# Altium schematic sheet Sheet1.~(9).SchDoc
size A4; SheetNumber: 2; SheetTotal: 2
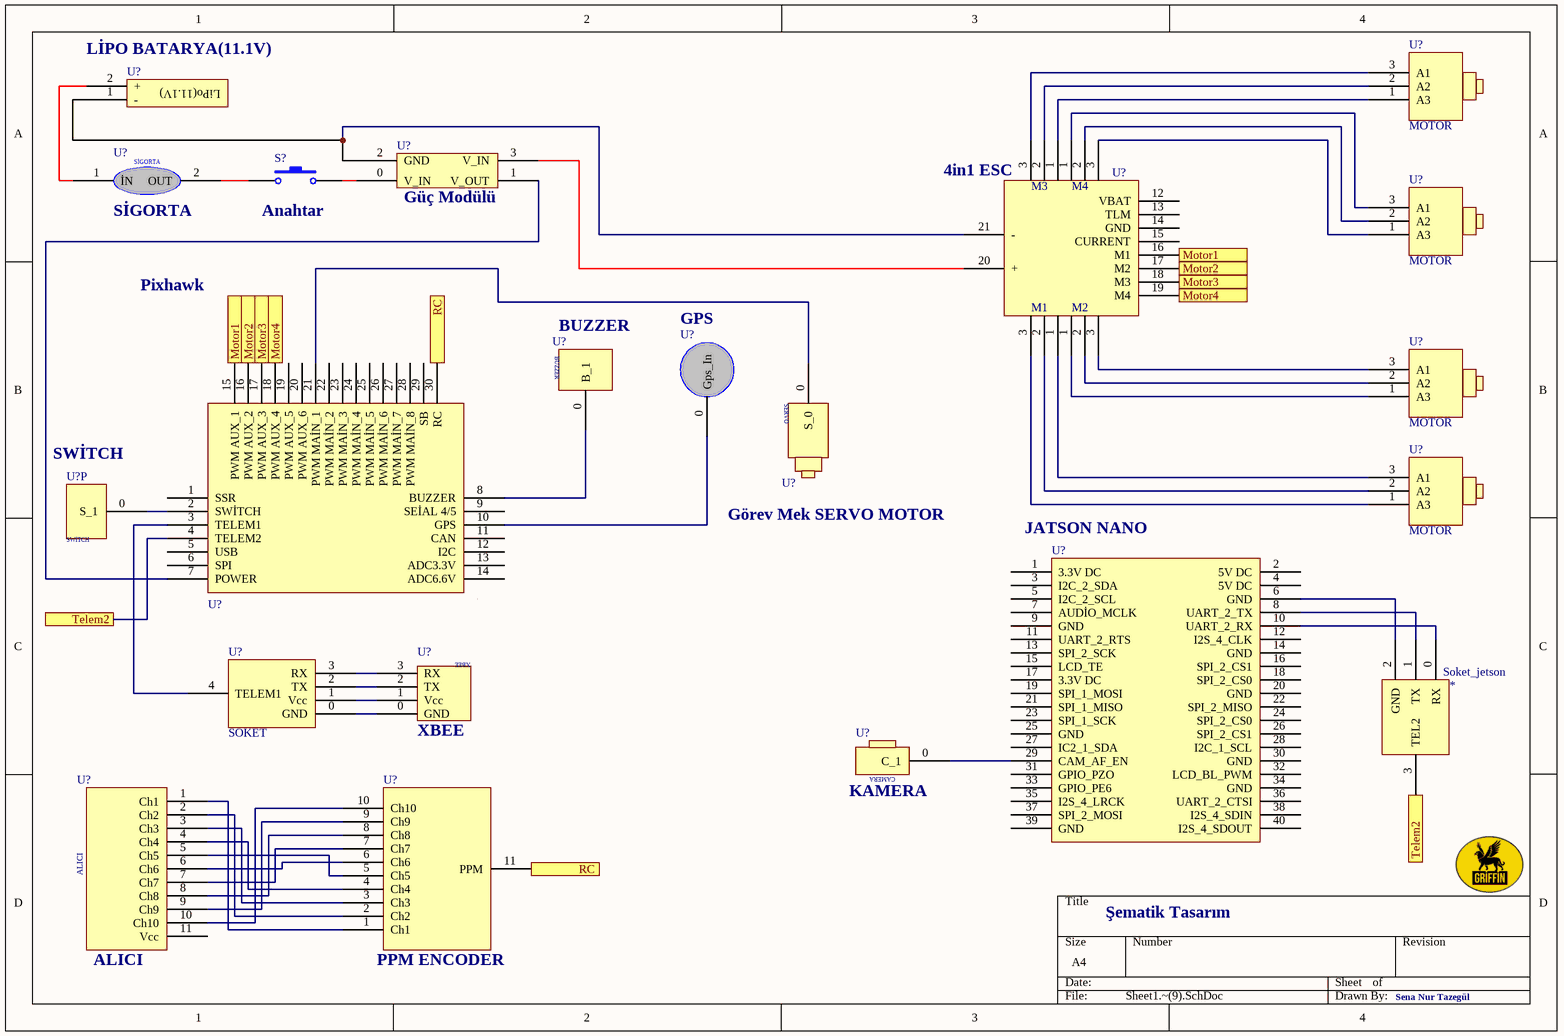
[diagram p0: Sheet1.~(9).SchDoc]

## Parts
(Parts that share a designator on the sheet are numbered #1, #2 ... from top to bottom, then left to right.)
*  Soket_jetson
S?  Anahtar  [SPST-2]
U?#1  Pixhawk
U?#2  LİPO BATARYA(11.1V)
U?#3  MOTOR
U?#4  (no value)
U?#5  SİGORTA
U?#6  4in1 ESC
U?#7  MOTOR
U?#8  BUZZER
U?#9  MOTOR
U?#10  GPS
U?#11  Görev Mek SERVO MOTOR
U?#12  MOTOR
U?#13  SOKET
U?#14  XBEE
U?#15  KAMERA
U?#16  ALICI
U?#17  JATSON NANO
U?#18  PPM ENCODER
U?P  SWİTCH

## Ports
Motor1, Motor2, Motor3, Motor4, RC, Telem2

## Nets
Motor1: U?#1.15(PWM_AUX_1) U?#6.16(M1) ; port Motor1
Motor2: U?#1.16(PWM_AUX_2) U?#6.17(M2) ; port Motor2
Motor3: U?#1.17(PWM_AUX_3) U?#6.18(M3) ; port Motor3
Motor4: U?#1.18(PWM_AUX_4) U?#6.19(M4) ; port Motor4
RC: U?#1.30(RC) U?#18.11(PPM) ; port RC
Telem2: *.3(TEL2) U?#1.4(TELEM2) ; port Telem2
Net*_0: *.0(RX) U?#17.10(UART_2_RX)
Net*_1: *.1(TX) U?#17.8(UART_2_TX)
Net*_2: *.2(GND) U?#17.6(GND)
NetS?_1: S?.1 U?#5.2(OUT)
NetS?_2: S?.2 U?#4.0(V_IN)
NetU?#1_2: U?#1.2(SWİTCH) U?P.0(S_1)
NetU?#1_3: U?#1.3(TELEM1) U?#13.4(TELEM1)
NetU?#1_7: U?#1.7(POWER) U?#4.1(V_OUT)
NetU?#1_8: U?#1.8(BUZZER) U?#8.0(B_1)
NetU?#1_10: U?#1.10(GPS) U?#10.0(Gps_In)
NetU?#1_21: U?#1.21(PWM_MAİN_1) U?#11.0(S_0)
NetU?#2_1: U?#2.1(-) U?#4.2(GND) U?#6.21(-)
NetU?#2_2: U?#2.2(+) U?#5.1(İN)
NetU?#3_1: U?#3.1(A3) U?#6.1
NetU?#3_2: U?#3.2(A2) U?#6.2
NetU?#3_3: U?#3.3(A1) U?#6.3
NetU?#4_3: U?#4.3(V_IN) U?#6.20(+)
NetU?#6_1: U?#6.1 U?#9.1(A3)
NetU?#6_1: U?#6.1 U?#12.3(A1)  [a separate net that carries the same name]
NetU?#6_1: U?#6.1 U?#7.3(A1)  [a separate net that carries the same name]
NetU?#6_2: U?#6.2 U?#9.2(A2)
NetU?#6_2: U?#6.2 U?#12.2(A2)  [a separate net that carries the same name]
NetU?#6_2: U?#6.2 U?#7.2(A2)  [a separate net that carries the same name]
NetU?#6_3: U?#6.3 U?#9.3(A1)
NetU?#6_3: U?#6.3 U?#12.1(A3)  [a separate net that carries the same name]
NetU?#6_3: U?#6.3 U?#7.1(A3)  [a separate net that carries the same name]
NetU?#13_0: U?#13.0(GND) U?#14.0(GND)
NetU?#13_1: U?#13.1(Vcc) U?#14.1(Vcc)
NetU?#13_2: U?#13.2(TX) U?#14.2(TX)
NetU?#13_3: U?#13.3(RX) U?#14.3(RX)
NetU?#15_0: U?#15.0(C_1) U?#17.29(CAM_AF_EN)
NetU?#16_1: U?#16.1(Ch1) U?#18.1(Ch1)
NetU?#16_2: U?#16.2(Ch2) U?#18.2(Ch2)
NetU?#16_3: U?#16.3(Ch3) U?#18.3(Ch3)
NetU?#16_4: U?#16.4(Ch4) U?#18.4(Ch4)
NetU?#16_5: U?#16.5(Ch5) U?#18.5(Ch5)
NetU?#16_6: U?#16.6(Ch6) U?#18.6(Ch6)
NetU?#16_7: U?#16.7(Ch7) U?#18.7(Ch7)
NetU?#16_8: U?#16.8(Ch8) U?#18.8(Ch8)
NetU?#16_9: U?#16.9(Ch9) U?#18.9(Ch9)
NetU?#16_10: U?#16.10(Ch10) U?#18.10(Ch10)

Not connected (* = marked no-connect by the designer): U?#1 1(SSR) 5(USB) 6(SPI) 9(SEİAL_4/5) 11(CAN) 12(I2C) 13(ADC3.3V) 14(ADC6.6V) 19(PWM_AUX_5) 20(PWM_AUX_6) 22(PWM_MAİN_2) 23(PWM_MAİN_3) 24(PWM_MAİN_4) 25(PWM_MAİN_5) 26(PWM_MAİN_6) 27(PWM_MAİN_7) 28(PWM_MAİN_8) 29(SB); U?#6 12(VBAT) 13(TLM) 14(GND) 15(CURRENT); U?#16 11(Vcc); U?#17 1(3.3V_DC) 2(5V_DC) 3(I2C_2_SDA) 4(5V_DC) 5(I2C_2_SCL) 7(AUDİO_MCLK) 9(GND) 11(UART_2_RTS) 12(I2S_4_CLK) 13(SPI_2_SCK) 14(GND) 15(LCD_TE) 16(SPI_2_CS1) 17(3.3V_DC) 18(SPI_2_CS0) 19(SPI_1_MOSI) 20(GND) 21(SPI_1_MISO) 22(SPI_2_MISO) 23(SPI_1_SCK) 24(SPI_2_CS0) 25(GND) 26(SPI_2_CS1) 27(IC2_1_SDA) 28(I2C_1_SCL) 30(GND) 31(GPIO_PZO) 32(LCD_BL_PWM) 33(GPIO_PE6) 34(GND) 35(I2S_4_LRCK) 36(UART_2_CTSI) 37(SPI_2_MOSI) 38(I2S_4_SDIN) 39(GND) 40(I2S_4_SDOUT)

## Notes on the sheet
- Şematik Tasarım
- Sena Nur Tazegül

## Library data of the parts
S? = SW-PB: Switch
U?#4 = GÜÇ MODÜLÜ
U?#11 = SERVO MOTOR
